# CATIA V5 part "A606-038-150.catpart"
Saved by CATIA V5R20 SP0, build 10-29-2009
Part number: A606-038-150
Source: Unknown
Property "ARTICLENO": "A606-038-150"
Property "BOMINFO": "A606-038-150"
Property "CODE": "A606-038-150"
Property "HOLES": "2"
Property "L": "150.000"
Property "L1": "25.000"
Property "L2": "100.000"
Property "LINA": "A606-038-150"
Property "NB": "A606-038-150"
Property "NBSYN": "$CODE."
Property "NN": "A606"
Property "NT": "Wear Plates, self-lubricating"
Property "SCREW": "2xM6"
Property "SUPPLIER": "CF"
Property "W": "38.000"
Bounding box of the stored display mesh (mm): x -19 to 19, y -5 to 5, z -75 to 75
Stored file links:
  C:\Users\Utente\Desktop\3D files A606\A606-038-150.catpart
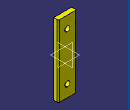
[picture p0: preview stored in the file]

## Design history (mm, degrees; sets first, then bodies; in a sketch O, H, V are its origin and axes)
Body1 "Geometry.1" (main body)
  Solid1 "A606-038-150.catpart": solid without history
